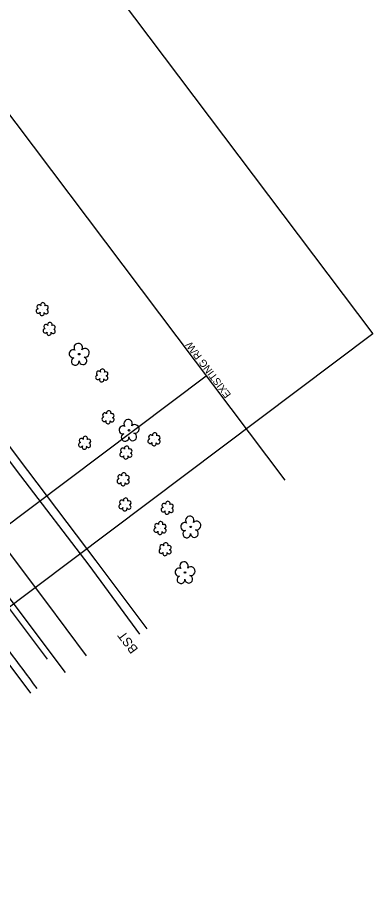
# Model space of a CAD drawing. Extents: x 1262092 to 1264624, y 774970 to 778314.
# Drawn here: x 1264468.8 to 1264624.2, y 775002.7 to 775381.8 of the extents above; entities that cross this region are included whole.
import ezdxf

# ---------------------------------------------------------------- set-up
doc = ezdxf.new("R2010")
doc.units = 0
for name, color, linetype in [('COGO Default Parcel', 7, 'Continuous'), ('Exist Boundary City Limits', 7, 'Continuous'), ('Exist Horizontal Alignment Tick Large', 7, 'Continuous'), ('Exist Horizontal Alignment Tick Small', 7, 'Continuous'), ('Exist Right of Way Line', 7, 'Continuous'), ('Exist Right of Way Line Text', 7, 'Continuous'), ('Exist Right of Way Width CELL', 7, 'Continuous'), ('Exist Roads EOP', 7, 'Continuous'), ('Exist Roads EOT', 7, 'Continuous'), ('Prop Horizontal Alignment', 7, 'Continuous')]:
    doc.layers.add(name, color=color, linetype=linetype)

msp = doc.modelspace()

# ---------------------------------------------------------------- linework, layer by layer
at = {"layer": 'COGO Default Parcel'}
for p, q in [((1263602.12, 776600.93), (1264624.2, 775243.33)), ((1264624.2, 775243.33), (1264304.64, 775002.74))]:
    msp.add_line(p, q, dxfattribs=at)
at = {"layer": 'Exist Boundary City Limits'}
msp.add_line((1264481.92, 775101.04), (1263870.58, 775912.68), dxfattribs=at)
at = {"layer": 'Exist Horizontal Alignment Tick Large'}
for p, q in [((1264479.69, 775253.94), (1264479.69, 775253.94)), ((1264482.75, 775245.31), (1264482.75, 775245.31)), ((1264505.77, 775224.92), (1264505.77, 775224.92)), ((1264508.53, 775206.63), (1264508.53, 775206.63)), ((1264498.25, 775195.45), (1264498.25, 775195.45)), ((1264528.64, 775197), (1264528.64, 775197)), ((1264516.36, 775191.19), (1264516.36, 775191.19)), ((1264515.11, 775179.5), (1264515.11, 775179.5)), ((1264515.92, 775168.47), (1264515.92, 775168.47)), ((1264534.38, 775167.03), (1264534.38, 775167.03)), ((1264531.27, 775158.16), (1264531.27, 775158.16)), ((1264533.48, 775148.9), (1264533.48, 775148.9))]:
    msp.add_line(p, q, dxfattribs=at)
for centre, radius, start, end in [((1264478.21, 775255.07), 0.968, 35.8908, 245.4216), ((1264479.92, 775255.98), 0.99, 334.8391, 200.4717), ((1264477.89, 775253.24), 0.955, 95.1099, 327.9534), ((1264479.56, 775252.26), 0.984, 151.2797, 21.387), ((1264481.33, 775253.01), 0.937, 204.9913, 73.4601), ((1264481.36, 775254.81), 0.929, 284.4567, 126.0861), ((1264480.95, 775244.61), 0.955, 95.1099, 327.9534), ((1264481.27, 775246.44), 0.968, 35.8908, 245.4216), ((1264482.98, 775247.35), 0.99, 334.8391, 200.4717), ((1264484.39, 775244.38), 0.937, 204.9913, 73.4601), ((1264484.42, 775246.18), 0.929, 284.4567, 126.0861), ((1264482.62, 775243.63), 0.984, 151.2797, 21.387), ((1264504.29, 775226.05), 0.968, 35.8908, 245.4216), ((1264506, 775226.96), 0.99, 334.8391, 200.4717), ((1264507.45, 775225.79), 0.929, 284.4567, 126.0861), ((1264503.97, 775224.22), 0.955, 95.1099, 327.9534), ((1264505.65, 775223.24), 0.984, 151.2797, 21.387), ((1264507.41, 775223.99), 0.937, 204.9913, 73.4601), ((1264506.73, 775205.92), 0.955, 95.1099, 327.9534), ((1264507.04, 775207.76), 0.968, 35.8908, 245.4216), ((1264508.76, 775208.67), 0.99, 334.8391, 200.4717), ((1264510.2, 775207.5), 0.929, 284.4567, 126.0861), ((1264508.4, 775204.95), 0.984, 151.2797, 21.387), ((1264510.16, 775205.7), 0.937, 204.9913, 73.4601), ((1264528.87, 775199.04), 0.99, 334.8391, 200.4717), ((1264496.45, 775194.75), 0.955, 95.1099, 327.9534), ((1264496.77, 775196.58), 0.968, 35.8908, 245.4216), ((1264498.48, 775197.5), 0.99, 334.8391, 200.4717), ((1264499.89, 775194.53), 0.937, 204.9913, 73.4601), ((1264499.92, 775196.32), 0.929, 284.4567, 126.0861), ((1264526.84, 775196.3), 0.955, 95.1099, 327.9534), ((1264527.16, 775198.13), 0.968, 35.8908, 245.4216), ((1264528.51, 775195.32), 0.984, 151.2797, 21.387), ((1264530.28, 775196.08), 0.937, 204.9913, 73.4601), ((1264530.32, 775197.87), 0.929, 284.4567, 126.0861), ((1264498.12, 775193.77), 0.984, 151.2797, 21.387), ((1264514.88, 775192.32), 0.968, 35.8908, 245.4216), ((1264516.59, 775193.23), 0.99, 334.8391, 200.4717), ((1264518.03, 775192.06), 0.929, 284.4567, 126.0861), ((1264514.56, 775190.49), 0.955, 95.1099, 327.9534), ((1264516.23, 775189.51), 0.984, 151.2797, 21.387), ((1264518, 775190.26), 0.937, 204.9913, 73.4601), ((1264513.63, 775180.63), 0.968, 35.8908, 245.4216), ((1264515.34, 775181.54), 0.99, 334.8391, 200.4717), ((1264516.78, 775180.37), 0.929, 284.4567, 126.0861), ((1264513.31, 775178.8), 0.955, 95.1099, 327.9534), ((1264514.98, 775177.82), 0.984, 151.2797, 21.387), ((1264516.75, 775178.57), 0.937, 204.9913, 73.4601), ((1264514.44, 775169.6), 0.968, 35.8908, 245.4216), ((1264516.15, 775170.51), 0.99, 334.8391, 200.4717), ((1264517.59, 775169.34), 0.929, 284.4567, 126.0861), ((1264532.89, 775168.16), 0.968, 35.8908, 245.4216), ((1264534.6, 775169.07), 0.99, 334.8391, 200.4717), ((1264514.12, 775167.77), 0.955, 95.1099, 327.9534), ((1264515.79, 775166.79), 0.984, 151.2797, 21.387), ((1264517.56, 775167.54), 0.937, 204.9913, 73.4601), ((1264532.57, 775166.32), 0.955, 95.1099, 327.9534), ((1264534.25, 775165.35), 0.984, 151.2797, 21.387), ((1264536.01, 775166.1), 0.937, 204.9913, 73.4601), ((1264536.05, 775167.9), 0.929, 284.4567, 126.0861), ((1264529.46, 775157.46), 0.955, 95.1099, 327.9534), ((1264529.78, 775159.29), 0.968, 35.8908, 245.4216), ((1264531.49, 775160.2), 0.99, 334.8391, 200.4717), ((1264532.9, 775157.23), 0.937, 204.9913, 73.4601), ((1264532.94, 775159.03), 0.929, 284.4567, 126.0861), ((1264531.14, 775156.48), 0.984, 151.2797, 21.387), ((1264532, 775150.03), 0.968, 35.8908, 245.4216), ((1264533.71, 775150.94), 0.99, 334.8391, 200.4717), ((1264535.15, 775149.77), 0.929, 284.4567, 126.0861), ((1264531.68, 775148.2), 0.955, 95.1099, 327.9534), ((1264533.35, 775147.22), 0.984, 151.2797, 21.387), ((1264535.12, 775147.97), 0.937, 204.9913, 73.4601)]:
    msp.add_arc(centre, radius, start, end, dxfattribs=at)
at = {"layer": 'Exist Horizontal Alignment Tick Small'}
for p, q in [((1264495.8, 775234.42), (1264495.8, 775234.42)), ((1264517.61, 775201.12), (1264517.61, 775201.12)), ((1264544.59, 775158.85), (1264544.59, 775158.85)), ((1264542.08, 775138.89), (1264542.08, 775138.89))]:
    msp.add_line(p, q, dxfattribs=at)
for centre in [(1264495.8, 775234.42), (1264517.61, 775201.12), (1264544.59, 775158.85), (1264542.08, 775138.89)]:
    msp.add_circle(centre, 0.326, dxfattribs=at)
for centre, radius, start, end in [((1264495.41, 775237.3), 1.86, 330.1651, 219.7134), ((1264493.19, 775234.58), 1.73, 62.6636, 279.3457), ((1264498.35, 775235.01), 1.9, 257.1011, 134.1999), ((1264494.09, 775231.3), 1.69, 111.5671, 6.231), ((1264497.47, 775231.52), 1.7, 181.2822, 74.56), ((1264515, 775201.28), 1.73, 62.6636, 279.3457), ((1264517.22, 775204), 1.86, 330.1651, 219.7134), ((1264520.16, 775201.71), 1.9, 257.1011, 134.1999), ((1264515.9, 775198), 1.69, 111.5671, 6.231), ((1264519.28, 775198.23), 1.7, 181.2822, 74.56), ((1264544.2, 775161.72), 1.86, 330.1651, 219.7134), ((1264547.14, 775159.44), 1.9, 257.1011, 134.1999), ((1264541.98, 775159), 1.73, 62.6636, 279.3457), ((1264546.26, 775155.95), 1.7, 181.2822, 74.56), ((1264542.88, 775155.73), 1.69, 111.5671, 6.231), ((1264541.69, 775141.76), 1.86, 330.1651, 219.7134), ((1264539.47, 775139.04), 1.73, 62.6636, 279.3457), ((1264544.62, 775139.48), 1.9, 257.1011, 134.1999), ((1264540.37, 775135.77), 1.69, 111.5671, 6.231), ((1264543.75, 775135.99), 1.7, 181.2822, 74.56)]:
    msp.add_arc(centre, radius, start, end, dxfattribs=at)
at = {"layer": 'Exist Right of Way Line'}
msp.add_line((1263590.4, 776500.74), (1264585.76, 775179.25), dxfattribs=at)
at = {"layer": 'Exist Right of Way Width CELL'}
msp.add_line((1264551.4, 775224.86), (1264435.17, 775137.32), dxfattribs=at)
at = {"layer": 'Exist Roads EOP'}
for points in [[(1264356.79, 775338.17), (1264383.65, 775302.46), (1264413.48, 775262.67), (1264443.98, 775222.14), (1264473.2, 775183.54), (1264503.06, 775144), (1264525.38, 775114.25)], [(1264356.79, 775338.17), (1264383.65, 775302.46), (1264413.48, 775262.67), (1264443.98, 775222.14), (1264473.2, 775183.54)], [(1264433.14, 775169.57), (1264461.51, 775132.64), (1264489.74, 775095.18)]]:
    msp.add_lwpolyline(points, dxfattribs=at)
msp.add_spline([(1264477.42, 775088.17), (1264452.84, 775121.14), (1264426.3, 775156.48), (1264397.98, 775193.76), (1264392.76, 775201.19), (1264391.11, 775205.53), (1264393.71, 775209.04), (1264394.88, 775209.86), (1264396.01, 775210.36), (1264396.53, 775210.44)], degree=3, dxfattribs=at)
at = {"layer": 'Exist Roads EOT'}
for points in [[(1264353.93, 775336.04), (1264380.37, 775300.68), (1264410.53, 775260.48), (1264440.99, 775219.76), (1264470.13, 775181.13), (1264500.1, 775142.08), (1264522.23, 775111.94)], [(1264368.24, 775276.07), (1264395.5, 775239.87), (1264426.84, 775198.42), (1264454.48, 775161.48), (1264481.03, 775126.28), (1264498.94, 775102.43)], [(1264474.61, 775086.14), (1264449.87, 775119.12), (1264423.43, 775154.47), (1264395, 775191.73), (1264389.21, 775199.49)]]:
    msp.add_lwpolyline(points, dxfattribs=at)

# ---------------------------------------------------------------- texts
at = {"layer": 'Exist Right of Way Line Text'}
msp.add_text('EXISTING R/W', height=3.2, rotation=126.9874, dxfattribs=at).set_placement((1264562.39, 775216.71))
at = {"layer": 'Prop Horizontal Alignment'}
msp.add_text('BST', height=4, rotation=126.9874, dxfattribs=at).set_placement((1264521.78, 775105.33))
msp.add_text('BST', height=4, rotation=126.9874, dxfattribs=at).set_placement((1264521.78, 775105.33))

doc.saveas('drawing.dxf')
